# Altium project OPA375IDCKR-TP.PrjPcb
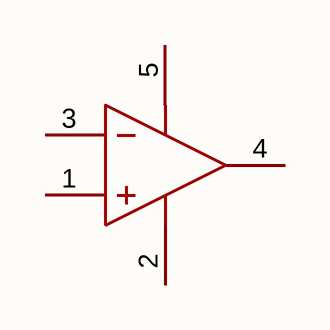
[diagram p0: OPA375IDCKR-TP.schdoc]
1 sheet, 1 parts. Net scope: global (net labels, ports and power ports of the same name join across sheets).

## Sheet OPA375IDCKR-TP.schdoc
size 127 x 101 mm

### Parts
U?  opa375idckr-tp  [SOT-353-5_L2.0-W1.6-P0.65-LS2.1-BL]  (value not drawn)

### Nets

Not connected (* = marked no-connect by the designer): U? 1(IN+) 2(VSS) 3(IN-) 4(OUT) 5(VDD)

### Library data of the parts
U? = opa375idckr-tp: Manufacturer: TECH PUBLIC(台舟); AddInBom: yes; ModelId: 09e153e3f5c7488aac8a155ea9f165d5; ModelTransform: 78.74,82.677,0,0,0,0,0,0,0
